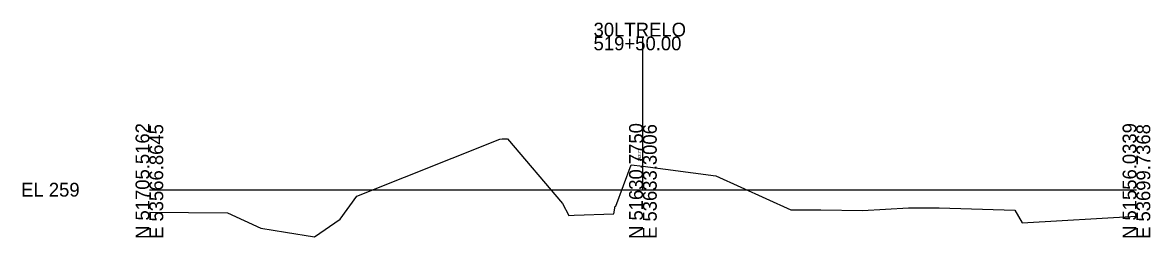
# Model space of a CAD drawing. Extents: x 3756 to 3985, y 89097 to 93134.
# Drawn here: x 3756 to 3984.5, y 90597.5 to 90641.1 of the extents above; entities that cross this region are included whole.
import ezdxf

# ---------------------------------------------------------------- set-up
doc = ezdxf.new("R2010")
doc.units = 0
for name, color, linetype in [('Level 10', 7, 'Continuous'), ('Level 60', 7, 'Continuous'), ('Level 63', 7, 'Continuous')]:
    doc.layers.add(name, color=color, linetype=linetype)

msp = doc.modelspace()

# ---------------------------------------------------------------- linework, layer by layer
at = {"layer": 'Level 60'}
for p, q in [((3823.73, 90605.87), (3852.72, 90617.45)), ((3852.72, 90617.45), (3853.17, 90617.5)), ((3853.17, 90617.5), (3854.27, 90617.52)), ((3854.27, 90617.52), (3865.42, 90604.35)), ((3876.19, 90603.84), (3879.29, 90612.24)), ((3879.29, 90612.24), (3881.68, 90611.92)), ((3881.68, 90611.92), (3896.44, 90609.96)), ((3896.44, 90609.96), (3911.68, 90603.07)), ((3820.32, 90601.21), (3823.73, 90605.87)), ((3781.68, 90602.63), (3797.52, 90602.5)), ((3797.52, 90602.5), (3804.25, 90599.34)), ((3865.42, 90604.35), (3866.68, 90601.92)), ((3875.81, 90602.29), (3876.04, 90603.84)), ((3876.04, 90603.84), (3876.19, 90603.84)), ((3911.68, 90603.07), (3917.7, 90603.07)), ((3917.7, 90603.07), (3926.18, 90602.95)), ((3926.18, 90602.95), (3935.52, 90603.48)), ((3935.52, 90603.48), (3941.68, 90603.48)), ((3941.68, 90603.48), (3957.06, 90602.98)), ((3957.06, 90602.98), (3958.53, 90600.47)), ((3815.17, 90597.62), (3820.32, 90601.21)), ((3866.68, 90601.92), (3867.77, 90601.99)), ((3867.77, 90601.99), (3875.81, 90602.29)), ((3958.53, 90600.47), (3981.68, 90601.79)), ((3804.25, 90599.34), (3809.26, 90598.57)), ((3809.26, 90598.57), (3815.17, 90597.62))]:
    msp.add_line(p, q, dxfattribs=at)
at = {"layer": 'Level 63'}
for p, q in [((3881.68, 90607.16), (3881.68, 90638.26)), ((3781.68, 90607.16), (3881.68, 90607.16)), ((3881.68, 90607.16), (3981.68, 90607.16))]:
    msp.add_line(p, q, dxfattribs=at)

# ---------------------------------------------------------------- texts
at = {"layer": 'Level 10'}
msp.add_text('263.77', height=0.6, rotation=90, dxfattribs=at).set_placement((3881.28, 90612.92))
at = {"layer": 'Level 63'}
for s, p in [('30LTRELO', (3871.68, 90638.26)), ('519+50.00', (3871.68, 90635.46)), ('EL 259', (3755.68, 90605.76))]:
    msp.add_text(s, height=2.8, dxfattribs=at).set_placement(p)
for s, p in [('N 51705.5162', (3781.68, 90597.16)), ('E 53566.8645', (3784.48, 90597.16)), ('N 51630.7750', (3881.68, 90597.16)), ('E 53633.3006', (3884.48, 90597.16)), ('N 51556.0339', (3981.68, 90597.16)), ('E 53699.7368', (3984.48, 90597.16))]:
    msp.add_text(s, height=2.8, rotation=90, dxfattribs=at).set_placement(p)

doc.saveas('drawing.dxf')
